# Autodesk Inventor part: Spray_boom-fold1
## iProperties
Created: 2007-04
Part Number: Spray_boom-fold1
Material: Steel, Mild
Document SubType Name: Sheet Metal
Designer: Admin
Density: 1 g/cm^3
Sheet Metal Rule: Default
Author: Admin
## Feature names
1. Bend3
2. Rectangular Pattern1
3. Plate1
4. Plate2
5. Bend1
6. Plate3
7. Bend2
8. Cut1
